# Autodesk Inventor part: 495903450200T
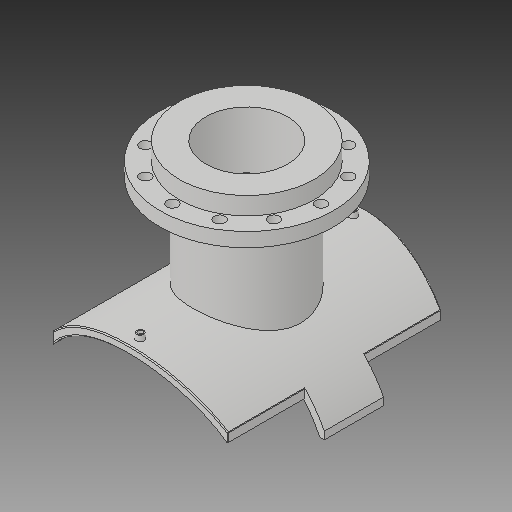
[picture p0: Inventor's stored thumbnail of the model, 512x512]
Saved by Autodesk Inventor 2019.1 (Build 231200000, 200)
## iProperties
Created: 2017-10
Part Number: 495903450200T
Material: Generic
Description: PLASSON FLANGED BRANCH SADDLE 450X200
Document SubType Name: Modeling
Designer: KIM
Mass: 2339.99 g
Surface Area: 3251.55 cm^2
Volume: 2339.99 cm^3
Density: 1 g/cm^3
Appearance: Default
Author: KIM
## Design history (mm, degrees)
derived "495904_495903.ipt"
feature "Solid1::495904_495903.ipt"
feature "Solid2::495904_495903.ipt"
tag "TaggingFeature1"
body "Solid1"
other parameters: "d1" = 15, "d2" = 348.3, "d4" = 0, "d6" = 117.5, "d7" = 0, "d12" = 250.6, "d13" = 14, "d14" = 211.5, "d16" = 5 deg, "d18" = 4, "d19" = 14, "d20" = 0, "d21" = 3, "d22" = 0, "d36" = 211.5, "d38" = 0, "d39" = 2, "d41" = 163, "d42" = 268, "d43" = 344, "d46" = 214.4, "d47" = 16, "d48" = 10.4, "d49" = 175, "d51" = 459, "d53" = 0, "d54" = 22, "d55" = 147.5, "d57" = 0, "d59" = 360 deg, "d61" = 28, "d63" = 0, "d67" = 15, "d68" = 125, "d70" = 0, "d71" = 2, "d72" = 387, "d_1" = 268, "B_" = 387, "x_" = 15, "D_" = 16, "DN_" = 163, "D_1" = 344, "t_" = 28, "s_" = 22, "Dp_" = 295
